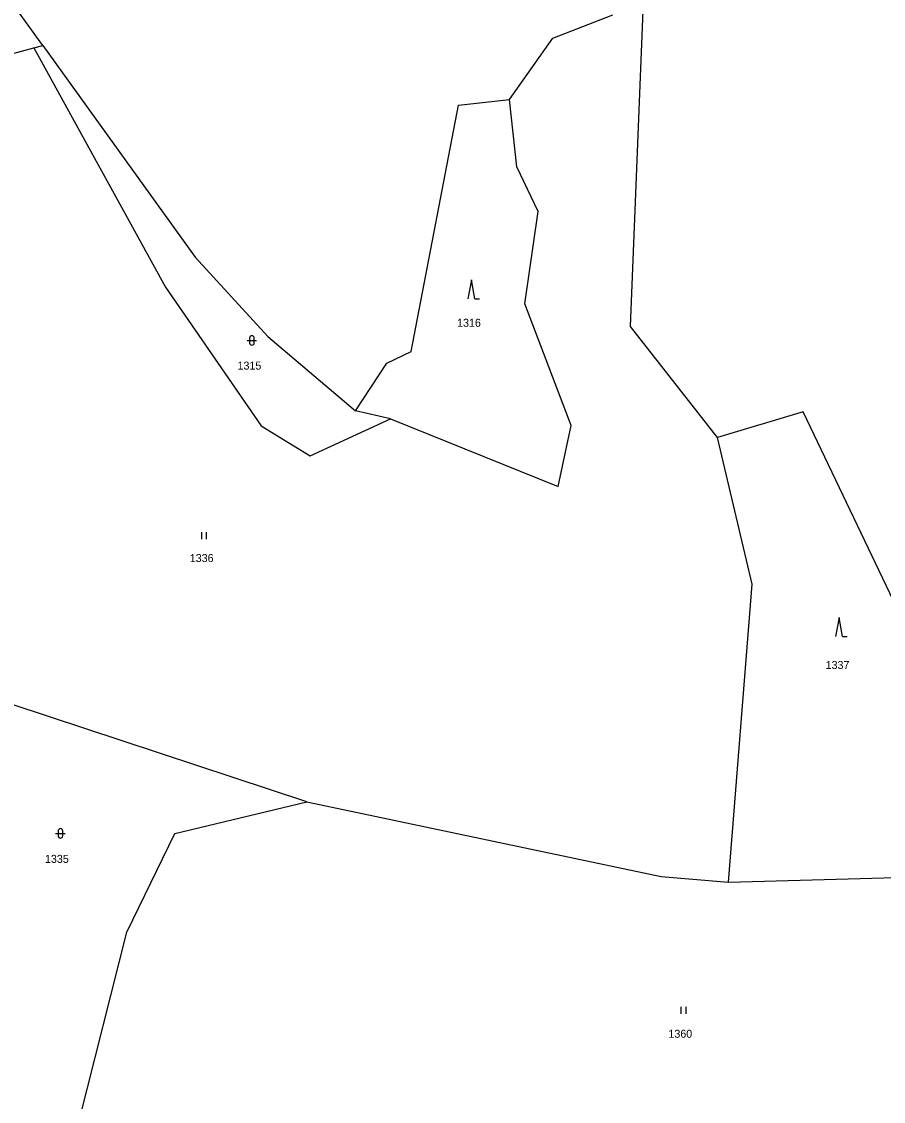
# Model space of a CAD drawing. Extents: x -520431 to -517205, y -1075927 to -1074013.
# Drawn here: x -517810.2 to -517627.2, y -1075237.3 to -1075007.9 of the extents above; entities that cross this region are included whole.
import ezdxf

# ---------------------------------------------------------------- set-up
doc = ezdxf.new("R2010")
doc.units = 0
for name, color, linetype in [('Hranice parcel', 7, 'Continuous'), ('Parcelní čísla', 7, 'Continuous'), ('Značky kultur', 7, 'Continuous')]:
    doc.layers.add(name, color=color, linetype=linetype)

msp = doc.modelspace()

# ---------------------------------------------------------------- linework, layer by layer
at = {"layer": 'Hranice parcel'}
for p, q in [((-517805.72, -1075013), (-517818.33, -1074995.49)), ((-517812.83, -1075014.89), (-517807.61, -1075013.5)), ((-517807.61, -1075013.5), (-517805.72, -1075013)), ((-517731.86, -1075092.33), (-517739.31, -1075090.63)), ((-517660.12, -1075190.75), (-517597.31, -1075189.04))]:
    msp.add_line(p, q, dxfattribs=at)
for points in [[(-517662.42, -1075096.28), (-517680.93, -1075072.7), (-517678.03, -1075000.2)], [(-517706.64, -1075024.44), (-517697.44, -1075011.46), (-517684.65, -1075006.47)], [(-517807.61, -1075013.5), (-517779.64, -1075064.31), (-517759.36, -1075093.78), (-517748.93, -1075100.15), (-517731.86, -1075092.33)], [(-517805.72, -1075013), (-517773.34, -1075057.97), (-517757.95, -1075074.78), (-517739.31, -1075090.63)], [(-517739.31, -1075090.63), (-517732.66, -1075080.49), (-517727.48, -1075077.99), (-517717.46, -1075025.69), (-517706.64, -1075024.44)], [(-517731.86, -1075092.33), (-517696.25, -1075106.72), (-517693.54, -1075093.7), (-517703.36, -1075067.84), (-517700.49, -1075048.23), (-517705.02, -1075038.77), (-517706.64, -1075024.44)], [(-517597.31, -1075189.04), (-517644.27, -1075090.8), (-517662.42, -1075096.28)], [(-517660.12, -1075190.75), (-517655.07, -1075127.42), (-517662.42, -1075096.28)], [(-517749.63, -1075173.65), (-517820.2, -1075150.37), (-517825.56, -1075149.12)], [(-517717.43, -1075259.69), (-517746.28, -1075251.33), (-517797.97, -1075241.49), (-517787.88, -1075201.39), (-517777.7, -1075180.44), (-517749.63, -1075173.65)], [(-517749.63, -1075173.65), (-517674.42, -1075189.56), (-517660.12, -1075190.75)]]:
    msp.add_lwpolyline(points, dxfattribs=at)
at = {"layer": 'Značky kultur'}
for p, q in [((-517714.71, -1075062.78), (-517715.46, -1075066.78)), ((-517713.96, -1075066.78), (-517714.71, -1075062.78)), ((-517713.96, -1075066.78), (-517712.96, -1075066.78)), ((-517762.32, -1075075.66), (-517760.32, -1075075.66)), ((-517761.82, -1075075.16), (-517761.82, -1075076.16)), ((-517760.82, -1075076.16), (-517760.82, -1075075.16)), ((-517771.94, -1075117.87), (-517771.94, -1075116.37)), ((-517770.94, -1075117.87), (-517770.94, -1075116.37)), ((-517636.62, -1075134.54), (-517637.37, -1075138.54)), ((-517635.87, -1075138.54), (-517636.62, -1075134.54)), ((-517635.87, -1075138.54), (-517634.87, -1075138.54)), ((-517802.49, -1075179.88), (-517802.49, -1075180.88)), ((-517801.49, -1075180.88), (-517801.49, -1075179.88)), ((-517802.99, -1075180.38), (-517800.99, -1075180.38)), ((-517670.12, -1075218.72), (-517670.12, -1075217.22)), ((-517669.12, -1075218.72), (-517669.12, -1075217.22))]:
    msp.add_line(p, q, dxfattribs=at)
for centre, start, end in [((-517761.32, -1075075.16), 0, 180), ((-517761.32, -1075076.16), 180, 359.9879), ((-517801.99, -1075179.88), 0, 180), ((-517801.99, -1075180.88), 180, 359.9879)]:
    msp.add_arc(centre, 0.5, start, end, dxfattribs=at)

# ---------------------------------------------------------------- texts
at = {"layer": 'Parcelní čísla'}
for s, p in [('1316', (-517717.74, -1075072.75)), ('1315', (-517764.37, -1075081.85)), ('1336', (-517774.51, -1075122.74)), ('1337', (-517639.47, -1075145.46)), ('1335', (-517805.26, -1075186.65)), ('1360', (-517672.86, -1075223.81))]:
    msp.add_text(s, height=1.7, dxfattribs=at).set_placement(p)

doc.saveas('drawing.dxf')
